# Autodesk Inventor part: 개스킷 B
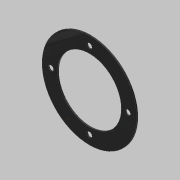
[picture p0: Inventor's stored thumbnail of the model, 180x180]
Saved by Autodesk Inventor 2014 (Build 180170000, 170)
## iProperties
Created: 2019-10
Part Number: 개스킷 B
Material: 고무
Document SubType Name: Modeling
Designer: mduedu
Density: 0.93 g/cm^3
Appearance: 고무 - 검은색 - 버전 1.1
Mass: 2.48562 g
Surface Area: 58.2294 cm^2
Volume: 2.67271 cm^3
Author: mduedu
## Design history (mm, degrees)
sketch "스케치1"
  geometry: C1 r 40 at (0, 0); C2 r 27 at (0, 0); 1 further point
  constraints: 2 centre point, 2 coincident
  dimensions: "d0" = 80 diameter of C1; "d1" = 54 diameter of C2
extrude "돌출1" new body sketch "스케치1" distance "d2" = 1; taper "d3" = 0 deg
sketch "스케치2" dims "d4" = 65
  geometry: C1 r 2.25 at (0, 32.5); 2 further points
  constraints: 2 vertical alignment, 1 centre point, 1 coincident, 2 other
  dimensions: "d5" = 4.5 diameter of C1
extrude "돌출2" cut sketch "스케치2" stored distance "d6" = 1; taper "d7" = 0 deg
node "솔리드1"
pattern_circular "원형 패턴1" dims angle "d9" = 360 deg
